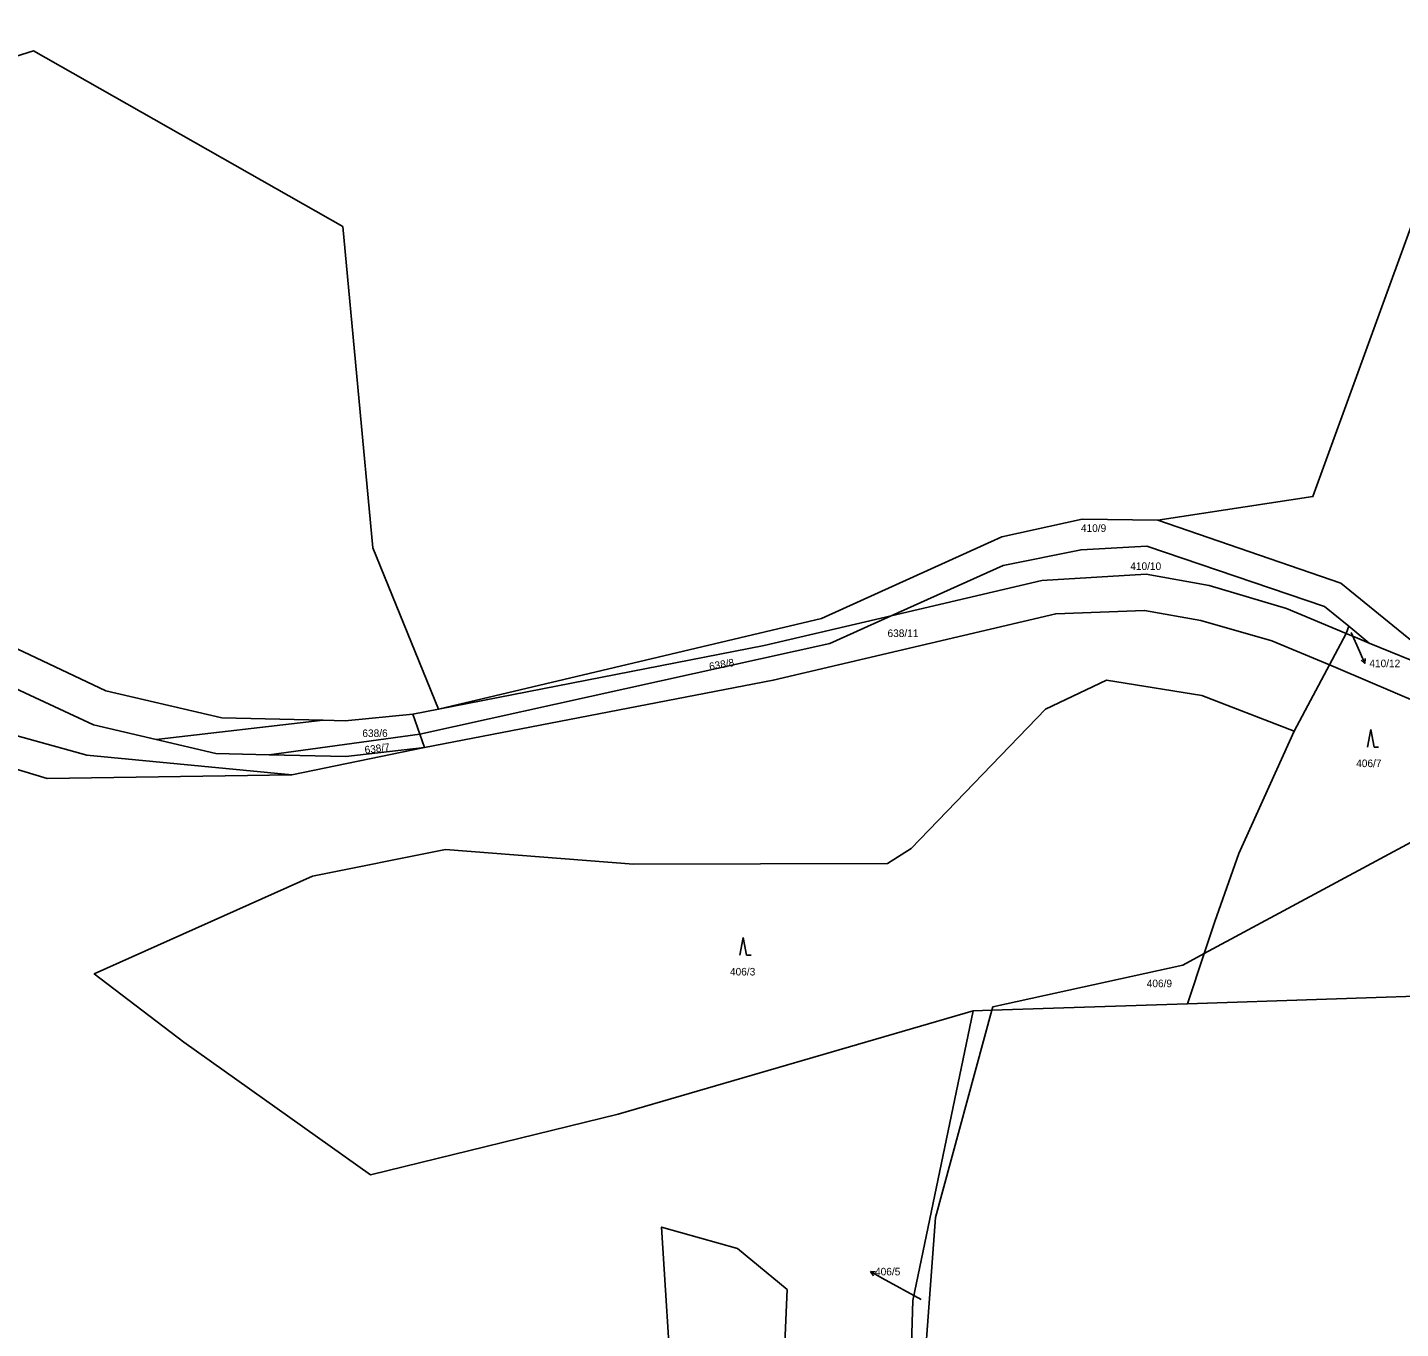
# Model space of a CAD drawing. Extents: x -744566 to -741843, y -1128407 to -1126744.
# Drawn here: x -744234.4 to -743925.6, y -1127273.4 to -1126980.7 of the extents above; entities that cross this region are included whole.
import ezdxf

# ---------------------------------------------------------------- set-up
doc = ezdxf.new("R2010")
doc.units = 0
for name, color, linetype in [('Hranice parcel', 7, 'Continuous'), ('Parcelní čísla', 7, 'Continuous'), ('Pop  PČ popisy', 7, 'Continuous'), ('Značky kultur', 7, 'Continuous')]:
    doc.layers.add(name, color=color, linetype=linetype)

msp = doc.modelspace()

# ---------------------------------------------------------------- linework, layer by layer
at = {"layer": 'Hranice parcel'}
for p, q in [((-743937.83, -1127117.06), (-743941.59, -1127124.09)), ((-743937.83, -1127117.06), (-743937.26, -1127115.42)), ((-743937.26, -1127115.42), (-743932.71, -1127119.19)), ((-743932.71, -1127119.19), (-743912.07, -1127127.67)), ((-743949.58, -1127139.05), (-743941.59, -1127124.09)), ((-744147.73, -1127135.2), (-744141.95, -1127134.07)), ((-744146.18, -1127139.69), (-744147.73, -1127135.2)), ((-744205.44, -1127140.9), (-744167.9, -1127136.55)), ((-744180.08, -1127144.3), (-744146.18, -1127139.69)), ((-744145.14, -1127142.72), (-744146.18, -1127139.69)), ((-744145.14, -1127142.72), (-744174.95, -1127148.84)), ((-743973.54, -1127200.34), (-743969.78, -1127189.05)), ((-743973.54, -1127200.34), (-744017.53, -1127201.77)), ((-744021.71, -1127201.91), (-744017.53, -1127201.77))]:
    msp.add_line(p, q, dxfattribs=at)
for points in [[(-743980.2, -1127091.58), (-743945.34, -1127086.24), (-743871.44, -1126883.01)], [(-744141.95, -1127134.07), (-744156.7, -1127097.78), (-744163.48, -1127025.52), (-744233.06, -1126986.04), (-744329.35, -1127016.37), (-744387.11, -1127024.48), (-744443.86, -1127022.41)], [(-744174.95, -1127148.84), (-744229.95, -1127149.65), (-744280.26, -1127134.47), (-744307.6, -1127117.99), (-744337.88, -1127091.55), (-744372.27, -1127079.71), (-744391.59, -1127080.09), (-744405.91, -1127076.95), (-744424.26, -1127065.45), (-744453.62, -1127036.45), (-744521.28, -1127003.63), (-744525.68, -1127001.45)], [(-744167.9, -1127136.55), (-744190.69, -1127136.02), (-744216.81, -1127129.91), (-744443.86, -1127022.41)], [(-744449.89, -1127030.17), (-744421.25, -1127060.37), (-744404.26, -1127071.47), (-744390.47, -1127074.49), (-744369.3, -1127074), (-744335.08, -1127085.8), (-744304.99, -1127111.68), (-744279.73, -1127128.15), (-744221.07, -1127144.42), (-744174.95, -1127148.84)], [(-744141.95, -1127134.07), (-744055.84, -1127113.65), (-744015.3, -1127095.33), (-743997.23, -1127091.35), (-743980.2, -1127091.58)], [(-743912.07, -1127127.67), (-743939.05, -1127105.74), (-743980.2, -1127091.58)], [(-744205.44, -1127140.9), (-744219.58, -1127137.62), (-744314.51, -1127093.33)], [(-744040.16, -1127113.06), (-744015.02, -1127101.72), (-743997.48, -1127098.21), (-743982.66, -1127097.37), (-743942.7, -1127110.94), (-743937.26, -1127115.42)], [(-744040.16, -1127113.06), (-744006.28, -1127105.14), (-743982.84, -1127103.69), (-743968.68, -1127106.23), (-743951.25, -1127111.41), (-743937.83, -1127117.06)], [(-744146.18, -1127139.69), (-744053.96, -1127119.29), (-744040.16, -1127113.06)], [(-743941.59, -1127124.09), (-743954.58, -1127118.72), (-743970.53, -1127114.1), (-743983.17, -1127111.85), (-744003.17, -1127112.62), (-744066.68, -1127127.58), (-744145.14, -1127142.72)], [(-744141.95, -1127134.07), (-744068.71, -1127119.74), (-744040.16, -1127113.06)], [(-743937.83, -1127117.06), (-743935.34, -1127118.11), (-743932.71, -1127119.19)], [(-743909.45, -1127137.8), (-743939.63, -1127124.9), (-743941.59, -1127124.09)], [(-744021.71, -1127201.91), (-744101.6, -1127225.16), (-744157.29, -1127238.81), (-744199.21, -1127208.98), (-744219.4, -1127193.61), (-744170.31, -1127171.65), (-744140.36, -1127165.65), (-744098.14, -1127168.91), (-744040.98, -1127168.78), (-744035.65, -1127165.39), (-744005.44, -1127134.1), (-743991.77, -1127127.58), (-743970.28, -1127130.97), (-743949.58, -1127139.05)], [(-744167.9, -1127136.55), (-744162.93, -1127136.66), (-744147.73, -1127135.2)], [(-743969.78, -1127189.05), (-743967.36, -1127181.8), (-743962.02, -1127166.55), (-743949.58, -1127139.05)], [(-744180.08, -1127144.3), (-744192.02, -1127144.02), (-744205.44, -1127140.9)], [(-744145.14, -1127142.72), (-744162.82, -1127144.7), (-744180.08, -1127144.3)], [(-743969.78, -1127189.05), (-743912.35, -1127158.14), (-743893.34, -1127151.92)], [(-743766.29, -1127237.43), (-743755.28, -1127247.25), (-743770.82, -1127248.95), (-743827.84, -1127223.67), (-743885.04, -1127166.35), (-743902.74, -1127158.4), (-743904.83, -1127167), (-743910.98, -1127198.27), (-743973.54, -1127200.34)], [(-744017.53, -1127201.77), (-744017.33, -1127201.04), (-743974.55, -1127191.62), (-743969.78, -1127189.05)], [(-744036.37, -1127301.78), (-744035.31, -1127267.07), (-744021.71, -1127201.91)], [(-744017.53, -1127201.77), (-744030.19, -1127248.42), (-744034.18, -1127302.06)], [(-744232.26, -1127558.32), (-744232.99, -1127497.42), (-744108.28, -1127499), (-744063.15, -1127499.85), (-744059.18, -1127436.28), (-744054.92, -1127320.35), (-744086.9, -1127328.53), (-744091.8, -1127250.55), (-744074.74, -1127255.35), (-744063.54, -1127264.6), (-744064.61, -1127288.79), (-744055.9, -1127290.74), (-744054.3, -1127303.37), (-744044.5, -1127305.2)]]:
    msp.add_lwpolyline(points, dxfattribs=at)
at = {"layer": 'Pop  PČ popisy'}
for p, q in [((-743936.69, -1127116.79), (-743934.84, -1127121.02)), ((-743934.84, -1127121.02), (-743933.619, -1127123.762)), ((-743933.619, -1127123.762), (-743934.484, -1127123.05)), ((-743933.619, -1127123.762), (-743933.569, -1127122.643)), ((-744042.18, -1127262.02), (-744044.805, -1127260.565)), ((-744044.805, -1127260.565), (-744043.686, -1127260.613)), ((-744044.805, -1127260.565), (-744044.172, -1127261.489)), ((-744033.46, -1127266.85), (-744042.18, -1127262.02))]:
    msp.add_line(p, q, dxfattribs=at)
at = {"layer": 'Značky kultur'}
for p, q in [((-743932.31, -1127138.63), (-743933.06, -1127142.63)), ((-743931.56, -1127142.63), (-743932.31, -1127138.63)), ((-743931.56, -1127142.63), (-743930.564, -1127142.63)), ((-744073.42, -1127185.39), (-744074.17, -1127189.39)), ((-744072.67, -1127189.39), (-744073.42, -1127185.39)), ((-744072.67, -1127189.39), (-744071.674, -1127189.39))]:
    msp.add_line(p, q, dxfattribs=at)

# ---------------------------------------------------------------- texts
at = {"layer": 'Parcelní čísla'}
for s, p in [('410/9', (-743997.5, -1127094.19)), ('410/10', (-743986.4, -1127102.76)), ('638/11', (-744040.99, -1127117.84)), ('410/12', (-743932.64, -1127124.62)), ('638/6', (-744159.09, -1127140.33)), ('406/7', (-743935.6, -1127147.1)), ('406/3', (-744076.42, -1127193.96)), ('406/9', (-743982.7, -1127196.6)), ('406/5', (-744043.8, -1127261.41))]:
    msp.add_text(s, height=1.7, dxfattribs=at).set_placement(p)
for s, rotation, p in [('638/8', 10, (-744080.952, -1127125.327)), ('638/7', 7, (-744158.486, -1127144.093))]:
    msp.add_text(s, height=1.7, rotation=rotation, dxfattribs=at).set_placement(p)

doc.saveas('drawing.dxf')
